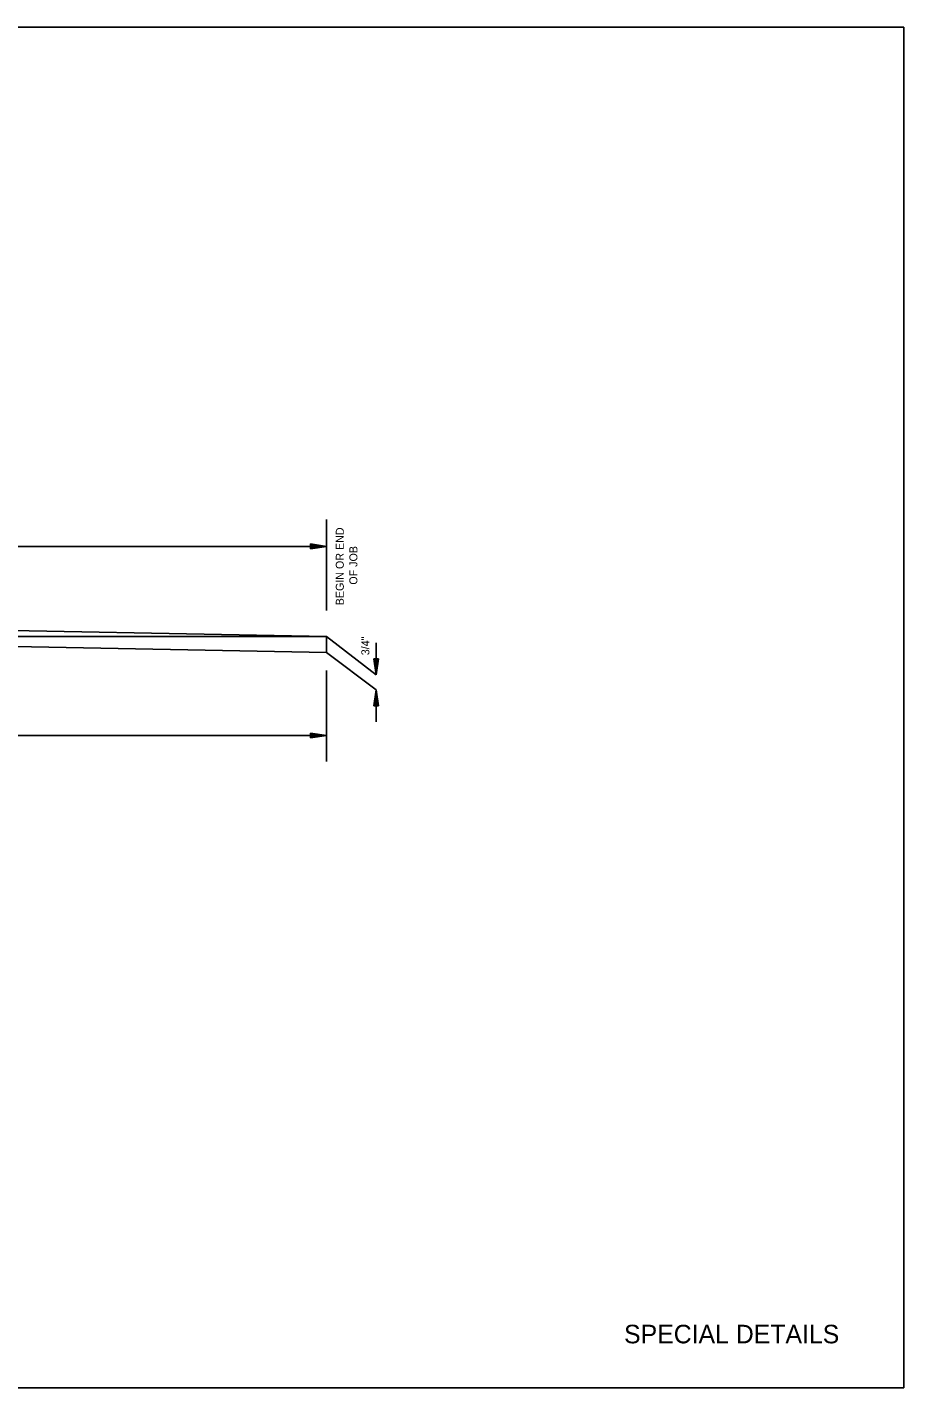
# Model space of a CAD drawing. Extents: x 8229 to 8749, y 14916 to 18021.
# Drawn here: x 8530.9 to 8746.8, y 14915.7 to 15251 of the extents above; entities that cross this region are included whole.
import ezdxf

# ---------------------------------------------------------------- set-up
doc = ezdxf.new("R2010")
doc.units = 0
for name, color, linetype in [('Default', 7, 'Continuous'), ('R_Border', 7, 'Continuous'), ('R_Draft', 7, 'Continuous'), ('R_Exist Surface', 7, 'Continuous')]:
    doc.layers.add(name, color=color, linetype=linetype)

msp = doc.modelspace()

# ---------------------------------------------------------------- linework, layer by layer
at = {"layer": 'Default'}
for points in [[(8746.76, 14915.68), (8746.76, 15250.96), (8228.6, 15250.96), (8228.6, 14915.68)], [(8228.6, 15250.96), (8228.6, 14915.68), (8746.76, 14915.68), (8746.76, 15250.96)]]:
    msp.add_lwpolyline(points, close=True, dxfattribs=at)
at = {"layer": 'R_Draft'}
for p, q in [((8600.64, 15123.62), (8604.58, 15123.02)), ((8600.64, 15123.62), (8600.64, 15122.43)), ((8600.64, 15123.52), (8603.92, 15123.02)), ((8600.64, 15123.42), (8603.24, 15123.02)), ((8600.64, 15123.32), (8602.59, 15123.02)), ((8600.64, 15123.22), (8601.92, 15123.02)), ((8600.64, 15123.12), (8601.26, 15123.02)), ((8600.64, 15122.43), (8604.58, 15123.02)), ((8600.64, 15122.83), (8601.92, 15123.02)), ((8600.64, 15122.63), (8603.24, 15123.02)), ((8600.64, 15122.53), (8603.92, 15123.02)), ((8600.64, 15122.73), (8602.59, 15123.02)), ((8600.64, 15122.93), (8601.26, 15123.02)), ((8616.24, 15095.33), (8616.83, 15091.39)), ((8617.42, 15095.33), (8616.24, 15095.33)), ((8616.34, 15095.33), (8616.83, 15092.04)), ((8616.44, 15095.33), (8616.83, 15092.72)), ((8616.54, 15095.33), (8616.83, 15093.38)), ((8616.64, 15095.33), (8616.83, 15094.05)), ((8616.74, 15095.33), (8616.83, 15094.71)), ((8617.42, 15095.33), (8616.83, 15091.39)), ((8617.02, 15095.33), (8616.83, 15094.05)), ((8617.22, 15095.33), (8616.83, 15092.72)), ((8617.32, 15095.33), (8616.83, 15092.04)), ((8617.12, 15095.33), (8616.83, 15093.38)), ((8616.92, 15095.33), (8616.83, 15094.71)), ((8616.24, 15083.72), (8616.83, 15087.67)), ((8617.42, 15083.72), (8616.83, 15087.67)), ((8616.34, 15083.72), (8616.83, 15087.01)), ((8616.44, 15083.72), (8616.83, 15086.33)), ((8616.54, 15083.72), (8616.83, 15085.67)), ((8616.64, 15083.72), (8616.83, 15085.01)), ((8616.74, 15083.72), (8616.83, 15084.35)), ((8617.32, 15083.72), (8616.83, 15087.01)), ((8617.22, 15083.72), (8616.83, 15086.33)), ((8617.12, 15083.72), (8616.83, 15085.67)), ((8617.02, 15083.72), (8616.83, 15085.01)), ((8616.92, 15083.72), (8616.83, 15084.35)), ((8616.24, 15083.72), (8617.42, 15083.72)), ((8600.64, 15077.02), (8604.58, 15076.43)), ((8600.64, 15077.02), (8600.64, 15075.84)), ((8600.64, 15076.93), (8603.92, 15076.43)), ((8600.64, 15076.83), (8603.24, 15076.43)), ((8600.64, 15076.73), (8602.59, 15076.43)), ((8600.64, 15076.62), (8601.92, 15076.43)), ((8600.64, 15076.53), (8601.26, 15076.43)), ((8600.64, 15075.84), (8604.58, 15076.43)), ((8600.64, 15076.24), (8601.92, 15076.43)), ((8600.64, 15076.04), (8603.24, 15076.43)), ((8600.64, 15075.94), (8603.92, 15076.43)), ((8600.64, 15076.14), (8602.59, 15076.43)), ((8600.64, 15076.34), (8601.26, 15076.43))]:
    msp.add_line(p, q, dxfattribs=at)
at = {"layer": 'R_Exist Surface'}
for p, q in [((8604.58, 15107.23), (8604.58, 15129.68)), ((8398.22, 15123.02), (8604.58, 15123.02)), ((8324.54, 15100.81), (8604.58, 15100.81)), ((8397.77, 15100.81), (8604.58, 15096.87)), ((8397.77, 15100.81), (8604.58, 15096.87)), ((8604.58, 15100.81), (8397.77, 15100.81)), ((8604.58, 15100.81), (8604.58, 15096.87)), ((8604.58, 15096.87), (8604.58, 15100.81)), ((8604.58, 15100.81), (8616.83, 15091.39)), ((8616.83, 15091.39), (8616.83, 15099.27)), ((8604.58, 15096.87), (8616.83, 15087.67)), ((8604.58, 15069.98), (8604.58, 15092.43)), ((8616.83, 15087.67), (8616.83, 15079.78)), ((8398.22, 15076.43), (8604.58, 15076.43))]:
    msp.add_line(p, q, dxfattribs=at)
msp.add_lwpolyline([(8324.54, 15104.76), (8397.77, 15104.76), (8604.58, 15100.81)], dxfattribs=at)

# ---------------------------------------------------------------- texts
at = {"layer": 'R_Border'}
msp.add_text('SPECIAL DETAILS', height=4.572, dxfattribs=at).set_placement((8677.87, 14926.64))
at = {"layer": 'R_Exist Surface'}
for s, height, p in [('BEGIN OR END', 1.9719, (8608.84, 15108.51)), ('OF JOB', 1.972, (8612.19, 15113.59)), ('3/4"', 1.972, (8615.14, 15096.2))]:
    msp.add_text(s, height=height, rotation=90, dxfattribs=at).set_placement(p)

doc.saveas('drawing.dxf')
